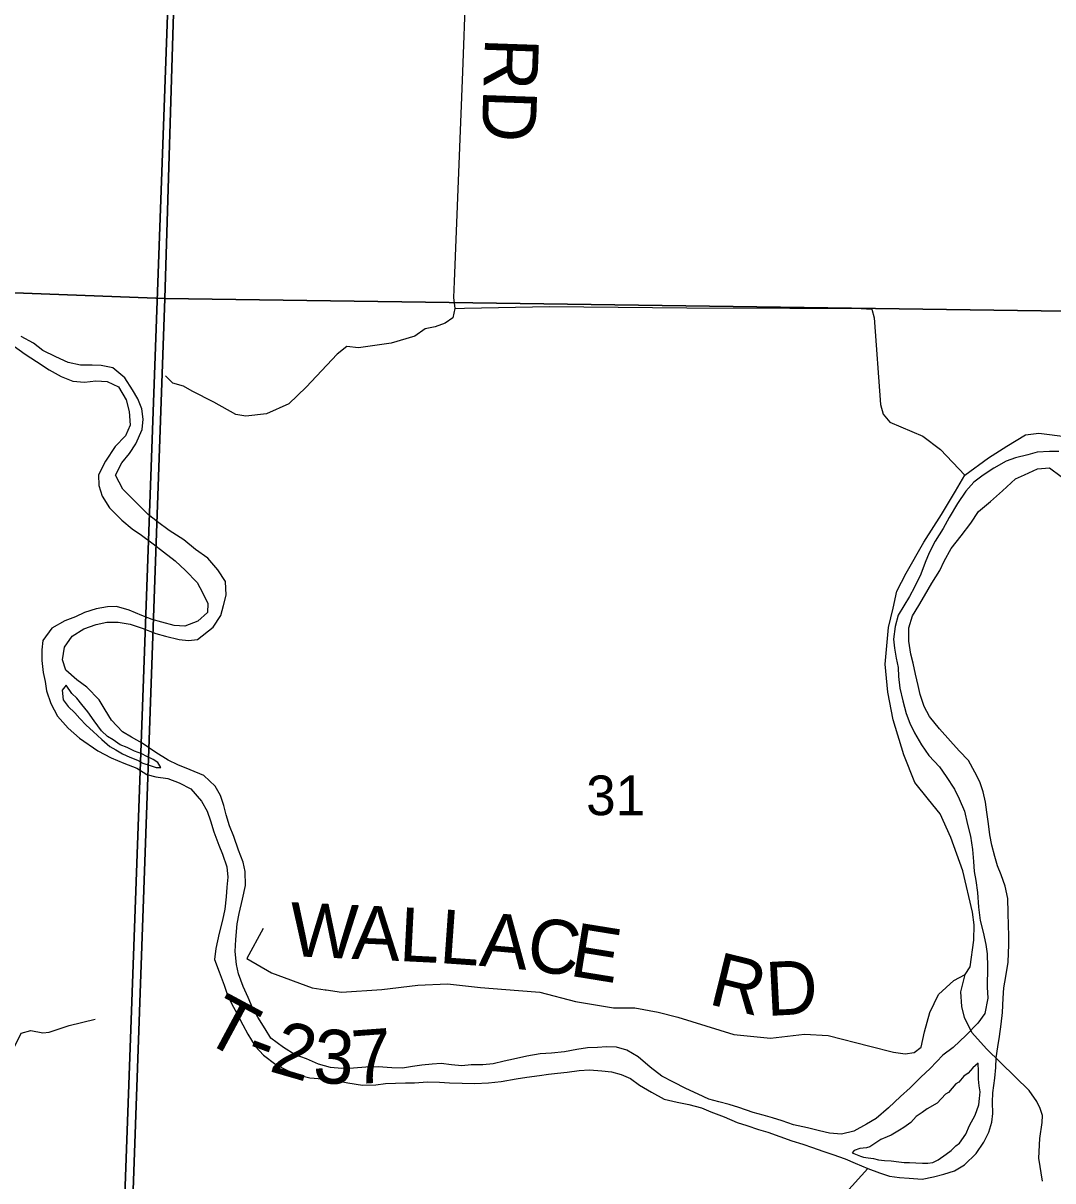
# Model space of a CAD drawing. Extents: x 0 to 34, y 0 to 22.
# Drawn here: x 5.884 to 6.971, y 17.741 to 18.962 of the extents above; entities that cross this region are included whole.
import ezdxf

# ---------------------------------------------------------------- set-up
doc = ezdxf.new("R2010")
doc.units = 0
for name, color, linetype in [('Default', 7, 'Continuous'), ('GM_X_County_Road', 7, 'Continuous'), ('GM_X_Major_River', 7, 'Continuous'), ('GM_X_Minor_River', 7, 'Continuous'), ('GM_X_Section', 7, 'Continuous'), ('GM_X_Section_Text', 7, 'Continuous'), ('GM_X_Township_Road', 7, 'Continuous'), ('GM_X_Township_Road_Text', 7, 'Continuous')]:
    doc.layers.add(name, color=color, linetype=linetype)

msp = doc.modelspace()

# ---------------------------------------------------------------- linework, layer by layer
at = {"layer": 'Default'}
msp.add_lwpolyline([(4.98, 17.7015), (5.0396, 17.6997), (5.1253, 17.6972), (5.2207, 17.6942), (5.2737, 17.6923), (5.3125, 17.691), (5.4195, 17.6873), (5.5532, 17.6849), (5.9893, 17.6676), (6.0568, 19.5343), (6.0632, 19.7108), (6.0696, 20.0002), (6.0777, 20.3704), (6.08, 20.4768), (6.0809, 20.5156), (6.0839, 20.7194), (6.0871, 20.9), (2.1, 20.9)], dxfattribs=at)
msp.add_lwpolyline([(8.9, 17.6104), (8.9, 20.9), (6.0871, 20.9), (6.0839, 20.7194), (6.0809, 20.5156), (6.08, 20.4768), (6.0777, 20.3704), (6.0696, 20.0002), (6.0632, 19.7108), (6.0568, 19.5343), (5.9893, 17.6676), (6.9889, 17.643), (7.0308, 17.6406), (8.0065, 17.6245)], close=True, dxfattribs=at)
at = {"layer": 'GM_X_County_Road'}
for points in [[(6.8778, 18.4853), (6.9027, 18.5036), (6.922, 18.5159), (6.9416, 18.5276), (6.9558, 18.5295), (6.9862, 18.5256)], [(6.9596, 17.7407), (6.9558, 17.765), (6.9568, 17.7857), (6.9593, 17.8026), (6.9596, 17.8099), (6.9573, 17.8173), (6.9538, 17.8248), (6.9457, 17.8362), (6.9004, 17.8803), (6.8849, 17.8975), (6.8774, 17.9132), (6.8745, 17.9249), (6.8734, 17.9402), (6.8781, 17.9587), (6.8832, 17.9668), (6.8872, 17.9948), (6.8875, 18.0111), (6.8859, 18.0242), (6.8756, 18.0678), (6.863, 18.1029), (6.8517, 18.128), (6.8393, 18.1432), (6.8251, 18.1612), (6.8135, 18.1904), (6.8022, 18.2273), (6.7963, 18.2564), (6.7935, 18.2858), (6.7971, 18.3244), (6.802, 18.3448), (6.806, 18.363), (6.8158, 18.382), (6.8344, 18.4145), (6.8531, 18.4436), (6.868, 18.4682), (6.8778, 18.4853)]]:
    msp.add_lwpolyline(points, dxfattribs=at)
at = {"layer": 'GM_X_Major_River'}
for points in [[(6.0977, 18.3729), (6.0895, 18.3852), (6.0791, 18.3975), (6.066, 18.4068), (6.0537, 18.4169), (6.0383, 18.4267), (6.0259, 18.436), (6.0162, 18.4438), (6.0013, 18.4585), (5.9894, 18.4705), (5.9817, 18.485), (5.9884, 18.4982), (5.9965, 18.5079), (6.0032, 18.5181), (6.0099, 18.5332), (6.0109, 18.5442), (6.0095, 18.5552), (6.0052, 18.5655), (5.9997, 18.5751), (5.9915, 18.5878), (5.9788, 18.5983), (5.9664, 18.6008), (5.9569, 18.6013), (5.9447, 18.6011), (5.9319, 18.604), (5.9187, 18.61), (5.9052, 18.6167), (5.8951, 18.6244), (5.8823, 18.6315)], [(5.8711, 18.6237), (5.8865, 18.6128), (5.8985, 18.605), (5.9116, 18.5964), (5.9244, 18.5893), (5.9368, 18.5842), (5.9489, 18.5832), (5.9611, 18.5845), (5.9729, 18.5839), (5.9849, 18.5784), (5.993, 18.5646), (5.9962, 18.5524), (5.9971, 18.5379), (5.9923, 18.5266), (5.9815, 18.5154), (5.9713, 18.5), (5.9639, 18.4857), (5.964, 18.4743), (5.9676, 18.4629), (5.9754, 18.4506), (5.9884, 18.4378), (5.9992, 18.4285), (6.009, 18.4219), (6.0213, 18.4126), (6.0322, 18.4044), (6.0445, 18.3947)], [(6.9769, 18.5101), (6.967, 18.5103), (6.9541, 18.5094), (6.9442, 18.5065), (6.9312, 18.5033), (6.9213, 18.5001), (6.9082, 18.4927), (6.8971, 18.4853), (6.8871, 18.4779), (6.8789, 18.4682), (6.87, 18.4554), (6.861, 18.4404), (6.8547, 18.4291), (6.8465, 18.4156), (6.8402, 18.4031), (6.8358, 18.393), (6.8314, 18.3809), (6.8247, 18.3669), (6.8192, 18.3572), (6.8133, 18.3474), (6.8075, 18.3376), (6.8042, 18.3255), (6.8024, 18.3123), (6.8034, 18.3028), (6.8051, 18.2921), (6.8072, 18.2822), (6.8078, 18.2727), (6.8091, 18.2605), (6.8123, 18.2471), (6.8158, 18.2338), (6.8198, 18.2235), (6.8245, 18.2135), (6.8319, 18.2008), (6.8397, 18.1897), (6.8508, 18.1777), (6.8579, 18.1674), (6.8667, 18.1539), (6.8718, 18.1439), (6.8773, 18.1309), (6.8805, 18.1168), (6.8836, 18.1046), (6.8857, 18.0905), (6.8869, 18.0776), (6.8875, 18.0673), (6.8892, 18.0578), (6.8909, 18.0449), (6.8921, 18.0296), (6.8938, 18.0156), (6.897, 18.0034), (6.8998, 17.9904), (6.9011, 17.9805), (6.9016, 17.9668), (6.9012, 17.9452), (6.9018, 17.9338), (6.8988, 17.9175), (6.8914, 17.9074), (6.879, 17.8947), (6.8655, 17.8816), (6.8544, 17.8734), (6.8412, 17.8596), (6.8312, 17.8503), (6.8199, 17.8391), (6.8099, 17.8298), (6.7972, 17.8179), (6.7841, 17.8067), (6.7741, 17.8008), (6.7607, 17.7934), (6.7477, 17.7902), (6.7348, 17.7912), (6.7242, 17.7937), (6.7118, 17.7969), (6.697, 17.8002), (6.685, 17.8043), (6.6748, 17.8075)], [(6.6096, 17.8139), (6.6239, 17.8084), (6.6375, 17.8024), (6.6477, 17.7992), (6.6601, 17.7952), (6.6699, 17.7924), (6.6824, 17.7876), (6.6952, 17.7832), (6.7069, 17.7796), (6.7171, 17.776), (6.728, 17.7724), (6.7386, 17.7688), (6.7514, 17.7643), (6.7619, 17.7596), (6.7755, 17.754), (6.7876, 17.7493), (6.7981, 17.7461), (6.8087, 17.7444), (6.819, 17.7438), (6.8326, 17.7428), (6.8448, 17.7452), (6.8555, 17.7481), (6.8669, 17.7517), (6.8773, 17.758), (6.8896, 17.7699), (6.8978, 17.7819), (6.903, 17.7925), (6.9062, 17.8027), (6.9071, 17.8121), (6.907, 17.8239), (6.9071, 17.8338), (6.9093, 17.8493), (6.9103, 17.8607), (6.9109, 17.8706), (6.9126, 17.8823), (6.9143, 17.8933), (6.9161, 17.9062), (6.9174, 17.9187), (6.9181, 17.9335), (6.919, 17.9445), (6.9208, 17.9566), (6.9233, 17.9717), (6.9241, 17.9903), (6.9242, 17.9998), (6.9237, 18.0101), (6.9235, 18.0238), (6.923, 18.0386), (6.9202, 18.0519), (6.9159, 18.0638), (6.9123, 18.0733), (6.9094, 18.0829), (6.9062, 18.0951), (6.9042, 18.1058), (6.9025, 18.1176), (6.9008, 18.1298), (6.8995, 18.1404), (6.897, 18.1511), (6.8934, 18.1618), (6.8883, 18.1721), (6.8817, 18.1844), (6.8716, 18.1945), (6.8627, 18.2045), (6.8508, 18.2176), (6.8404, 18.2307), (6.8349, 18.2411), (6.8306, 18.2537), (6.8285, 18.2632), (6.8257, 18.2754), (6.8232, 18.2868), (6.8207, 18.2964), (6.8187, 18.3101), (6.8186, 18.3241), (6.8226, 18.337), (6.8293, 18.3479), (6.8352, 18.358), (6.843, 18.3712), (6.8512, 18.3847), (6.8559, 18.3945), (6.8634, 18.4077), (6.8739, 18.4212), (6.884, 18.4346), (6.8922, 18.4467), (6.9049, 18.4574), (6.9176, 18.4686), (6.9312, 18.4813), (6.9407, 18.4857), (6.9545, 18.4919), (6.9671, 18.4928), (6.9794, 18.4839)], [(6.0445, 18.3947), (6.0557, 18.3846), (6.0677, 18.3719), (6.0735, 18.3615), (6.079, 18.35), (6.0788, 18.3405), (6.0684, 18.3312), (6.055, 18.3261), (6.0437, 18.3267), (6.0305, 18.33), (6.0203, 18.3328), (6.0093, 18.3372), (5.9961, 18.3427), (5.9829, 18.3468), (5.9734, 18.3462), (5.9613, 18.3441), (5.949, 18.3402), (5.9395, 18.3358), (5.9284, 18.3314), (5.9146, 18.3237), (5.9052, 18.3109), (5.9039, 18.3011), (5.9041, 18.2897), (5.9054, 18.2771), (5.9075, 18.2676), (5.9088, 18.2577), (5.9135, 18.2443), (5.9205, 18.2309), (5.9316, 18.2182), (5.9436, 18.2077), (5.9631, 18.1944), (5.977, 18.187), (5.9905, 18.1814), (6.0041, 18.1763), (6.0146, 18.1696), (6.0244, 18.1672), (6.0369, 18.1654), (6.049, 18.1607), (6.061, 18.1544), (6.0725, 18.1413), (6.0784, 18.1309), (6.082, 18.1206), (6.0856, 18.1091), (6.0907, 18.095), (6.0947, 18.0854), (6.0993, 18.072), (6.1003, 18.0614), (6.0993, 18.0508), (6.0984, 18.0405), (6.097, 18.0276), (6.0945, 18.0159), (6.0912, 18.0023), (6.0875, 17.986), (6.0862, 17.9743), (6.0909, 17.9613), (6.0963, 17.9475), (6.0995, 17.938), (6.1043, 17.9272), (6.1098, 17.9177), (6.116, 17.9054), (6.1212, 17.8958), (6.1289, 17.8831), (6.1378, 17.8735), (6.1509, 17.8638), (6.1633, 17.8575), (6.1731, 17.8531), (6.1867, 17.8498), (6.2, 17.8485), (6.2144, 17.8467), (6.2269, 17.8442), (6.2424, 17.842), (6.2564, 17.8422), (6.2667, 17.8435), (6.2769, 17.8441), (6.2876, 17.8443), (6.2971, 17.8445), (6.3107, 17.8454), (6.3236, 17.8452), (6.3339, 17.8442), (6.3608, 17.8437), (6.3752, 17.8442), (6.3886, 17.8459), (6.4042, 17.8487), (6.4156, 17.8504), (6.4289, 17.852), (6.4384, 17.8534), (6.4479, 17.8544), (6.4582, 17.8557), (6.4707, 17.8574), (6.4818, 17.8579), (6.4946, 17.857), (6.5049, 17.856), (6.5151, 17.8532), (6.5249, 17.8488), (6.5346, 17.8418), (6.547, 17.8344), (6.5605, 17.8273), (6.5741, 17.824), (6.5866, 17.8215), (6.5998, 17.8179), (6.6096, 17.8139)], [(6.6748, 17.8075), (6.665, 17.8103), (6.6544, 17.8131), (6.6393, 17.8183), (6.6291, 17.8216), (6.6182, 17.8244), (6.6076, 17.8273), (6.5963, 17.8324), (6.5835, 17.8383), (6.5703, 17.845), (6.5579, 17.8513), (6.5456, 17.861), (6.5329, 17.8719), (6.5212, 17.8789), (6.5103, 17.8821), (6.4997, 17.8823), (6.4902, 17.8817), (6.4795, 17.8812), (6.4685, 17.8794), (6.4552, 17.877), (6.4415, 17.8757), (6.4297, 17.8748), (6.4156, 17.8724), (6.4015, 17.8692), (6.3916, 17.8671), (6.3802, 17.8643), (6.3691, 17.8633), (6.357, 17.8632), (6.3471, 17.8622), (6.3361, 17.8632), (6.3251, 17.8649), (6.3156, 17.8639), (6.305, 17.863), (6.2951, 17.8616), (6.2844, 17.8599), (6.2731, 17.8601), (6.2587, 17.8611), (6.2458, 17.861), (6.2328, 17.8597), (6.2203, 17.8595), (6.2086, 17.8605), (6.1957, 17.8641), (6.1833, 17.8696), (6.1712, 17.874), (6.1588, 17.8815), (6.1457, 17.8916), (6.1395, 17.9012), (6.1317, 17.9135), (6.1262, 17.9234), (6.1215, 17.9342), (6.1164, 17.946), (6.1113, 17.9594), (6.1092, 17.9693), (6.108, 17.983), (6.1086, 17.9955), (6.11, 18.0122), (6.1121, 18.0228), (6.1158, 18.0379), (6.1187, 18.0523), (6.1186, 18.0671), (6.1165, 18.0771), (6.1114, 18.0897), (6.1064, 18.1042), (6.102, 18.1153), (6.0985, 18.1271), (6.096, 18.1367), (6.0924, 18.1474), (6.0869, 18.1573), (6.0749, 18.1686), (6.0606, 18.1745), (6.0474, 18.1797), (6.0373, 18.1848), (6.0241, 18.1926), (6.0099, 18.2027), (5.9986, 18.209), (5.9889, 18.2145), (5.9773, 18.2269), (5.9707, 18.2376), (5.9644, 18.2484), (5.9514, 18.2615), (5.9409, 18.2693), (5.9293, 18.2797), (5.9257, 18.2904), (5.9279, 18.3037), (5.9361, 18.3153), (5.9483, 18.3231), (5.9613, 18.3278), (5.9724, 18.3302), (5.9845, 18.33), (5.997, 18.3279), (6.0098, 18.3239), (6.0242, 18.3183), (6.0344, 18.3155), (6.0487, 18.3118), (6.0586, 18.3109), (6.0681, 18.3119), (6.0846, 18.3249), (6.0928, 18.3372), (6.0957, 18.3478), (6.0985, 18.3588), (6.0977, 18.3729)], [(5.9298, 18.2638), (5.9255, 18.2585), (5.9265, 18.2483), (5.9317, 18.2413), (5.9388, 18.2344), (5.944, 18.2286), (5.9507, 18.2216), (5.9581, 18.215), (5.9671, 18.2065), (5.9757, 18.1992), (5.9821, 18.1956), (5.9892, 18.1913), (5.9967, 18.1878)], [(5.9967, 18.1878), (6.005, 18.1846), (6.0106, 18.1815), (6.0182, 18.179), (6.0246, 18.177), (6.0295, 18.1769), (6.0262, 18.1823), (6.0213, 18.1854), (6.0146, 18.1886), (6.0093, 18.1914), (6.0018, 18.1941), (5.9939, 18.1981), (5.9867, 18.2009), (5.9792, 18.2059), (5.9732, 18.2095), (5.9669, 18.2157), (5.9591, 18.226), (5.9524, 18.2357), (5.9461, 18.2434), (5.9409, 18.2499), (5.9357, 18.2549), (5.9298, 18.2638)], [(6.7668, 17.7751), (6.761, 17.7729), (6.7587, 17.7707), (6.7678, 17.7671), (6.7708, 17.7659), (6.7757, 17.7654), (6.7814, 17.7646), (6.7867, 17.763), (6.7931, 17.7625), (6.7999, 17.762), (6.8079, 17.7611), (6.8136, 17.7602), (6.8193, 17.7605), (6.8261, 17.76), (6.8329, 17.7595), (6.8386, 17.7598), (6.8439, 17.7604), (6.8497, 17.763), (6.8581, 17.7693), (6.8631, 17.773), (6.8682, 17.7779), (6.872, 17.7808), (6.8786, 17.7902), (6.8826, 17.7993), (6.8885, 17.8102), (6.8925, 17.8211), (6.893, 17.828), (6.8939, 17.8348), (6.8929, 17.8412), (6.8922, 17.8481), (6.892, 17.8568), (6.8918, 17.8652)], [(6.8918, 17.8652), (6.886, 17.86), (6.8813, 17.8547), (6.8767, 17.8514), (6.8713, 17.845), (6.8682, 17.8432), (6.8605, 17.8342), (6.8574, 17.8324), (6.8485, 17.823), (6.8378, 17.8168), (6.8328, 17.8131), (6.8262, 17.809), (6.8208, 17.8026), (6.8135, 17.7974), (6.8089, 17.7945), (6.8001, 17.7893), (6.7959, 17.7875), (6.789, 17.7846), (6.7774, 17.7768), (6.774, 17.7757), (6.7668, 17.7751)]]:
    msp.add_lwpolyline(points, dxfattribs=at)
at = {"layer": 'GM_X_Minor_River'}
msp.add_lwpolyline([(6.7755, 17.754), (6.7521, 17.7285)], dxfattribs=at)
at = {"layer": 'GM_X_Section'}
for points in [[(6.0653, 19.7127), (6.0336, 18.6715), (5.0264, 18.7096), (5.0674, 19.7096)], [(6.9929, 19.6861), (7.008, 18.6577), (6.0336, 18.6715), (6.0653, 19.7127)], [(5.0264, 18.7096), (6.0336, 18.6715), (5.9983, 17.6719), (4.989, 17.6982)], [(6.0336, 18.6715), (7.008, 18.6577), (7.0009, 17.6487), (5.9983, 17.6719)]]:
    msp.add_lwpolyline(points, close=True, dxfattribs=at)
at = {"layer": 'GM_X_Township_Road'}
for points in [[(6.374, 19.7027), (6.3556, 19.1693), (6.3545, 19.1185), (6.3509, 18.9967), (6.3479, 18.9106), (6.3388, 18.6893), (6.3382, 18.6726), (6.3398, 18.661), (6.3498, 18.6612)], [(6.3398, 18.661), (6.3377, 18.6512), (6.3295, 18.6456), (6.3188, 18.6417), (6.3082, 18.6395), (6.2973, 18.6319), (6.2724, 18.6244), (6.2382, 18.6193), (6.2258, 18.6209), (6.2156, 18.6128), (6.1827, 18.5779), (6.1644, 18.5603), (6.141, 18.5498), (6.1193, 18.5474), (6.1088, 18.5491), (6.0855, 18.5621), (6.0627, 18.5739), (6.0533, 18.5792), (6.042, 18.5823), (6.0344, 18.5901)], [(6.3498, 18.6612), (6.4397, 18.6632), (6.5844, 18.6616), (6.6932, 18.6613), (6.7627, 18.6613), (6.7795, 18.6601), (6.7822, 18.6511), (6.7886, 18.5596), (6.7915, 18.5494), (6.7985, 18.5412), (6.8335, 18.5264), (6.8519, 18.5124), (6.8778, 18.4853)], [(6.1374, 18.0071), (6.1204, 17.9754), (6.1461, 17.9604), (6.189, 17.9446), (6.203, 17.9426)], [(6.203, 17.9426), (6.204, 17.9424), (6.22, 17.9401), (6.2627, 17.9429), (6.3005, 17.9473), (6.3321, 17.9486), (6.3666, 17.9448), (6.4068, 17.9419), (6.4292, 17.94), (6.4669, 17.93), (6.507, 17.9234), (6.5295, 17.9234), (6.554, 17.9188), (6.5748, 17.9135), (6.634, 17.8954), (6.6726, 17.8913), (6.7087, 17.8956), (6.7336, 17.8943), (6.7773, 17.8831), (6.8023, 17.8768), (6.8147, 17.8748), (6.8244, 17.8763), (6.8315, 17.8821), (6.8351, 17.8982), (6.8408, 17.9184), (6.8499, 17.9376), (6.8662, 17.9521), (6.8781, 17.9587)], [(5.6715, 17.8987), (5.6867, 17.8903), (5.7006, 17.8844), (5.719, 17.8791), (5.7406, 17.8719), (5.7595, 17.8653), (5.7756, 17.86), (5.7955, 17.8558), (5.8142, 17.8558), (5.8282, 17.8575), (5.8535, 17.8642), (5.8683, 17.8685), (5.8823, 17.8966), (5.8923, 17.8997), (5.9051, 17.897), (5.9116, 17.8979), (5.9328, 17.9048), (5.9604, 17.9115)]]:
    msp.add_lwpolyline(points, dxfattribs=at)

# ---------------------------------------------------------------- texts
at = {"layer": 'GM_X_Section_Text'}
msp.add_text('31', height=0.04186, rotation=0, dxfattribs=at).set_placement((6.4782, 18.1266))
at = {"layer": 'GM_X_Township_Road_Text'}
for s, height, rotation, p in [('RD', 0.05682, 268.0255, (6.3717, 18.9471)), ('W', 0.0568, 357.4483, (6.1646, 17.9781)), ('A', 0.0568, 357.4494, (6.2304, 17.9751)), ('L', 0.0568, 357.1403, (6.2802, 17.9729)), ('L', 0.0568, 356.0068, (6.3224, 17.9708)), ('A', 0.0568, 354.9409, (6.3645, 17.9679)), ('C', 0.0568, 352.4729, (6.4137, 17.9635)), ('E', 0.0568, 350.8022, (6.4595, 17.9575)), ('R', 0.0568, 346.1102, (6.6058, 17.9277)), ('D', 0.0568, 2.965, (6.6689, 17.9148)), ('T', 0.0568, 331.7644, (6.0712, 17.8902)), ('2', 0.0568, 343.8912, (6.1426, 17.857)), ('3', 0.0568, 356.1038, (6.1892, 17.845)), ('7', 0.0568, 4.2556, (6.2329, 17.8426)), ('-', 0.0568, 339.5079, (6.1163, 17.8667))]:
    msp.add_text(s, height=height, rotation=rotation, dxfattribs=at).set_placement(p)

doc.saveas('drawing.dxf')
